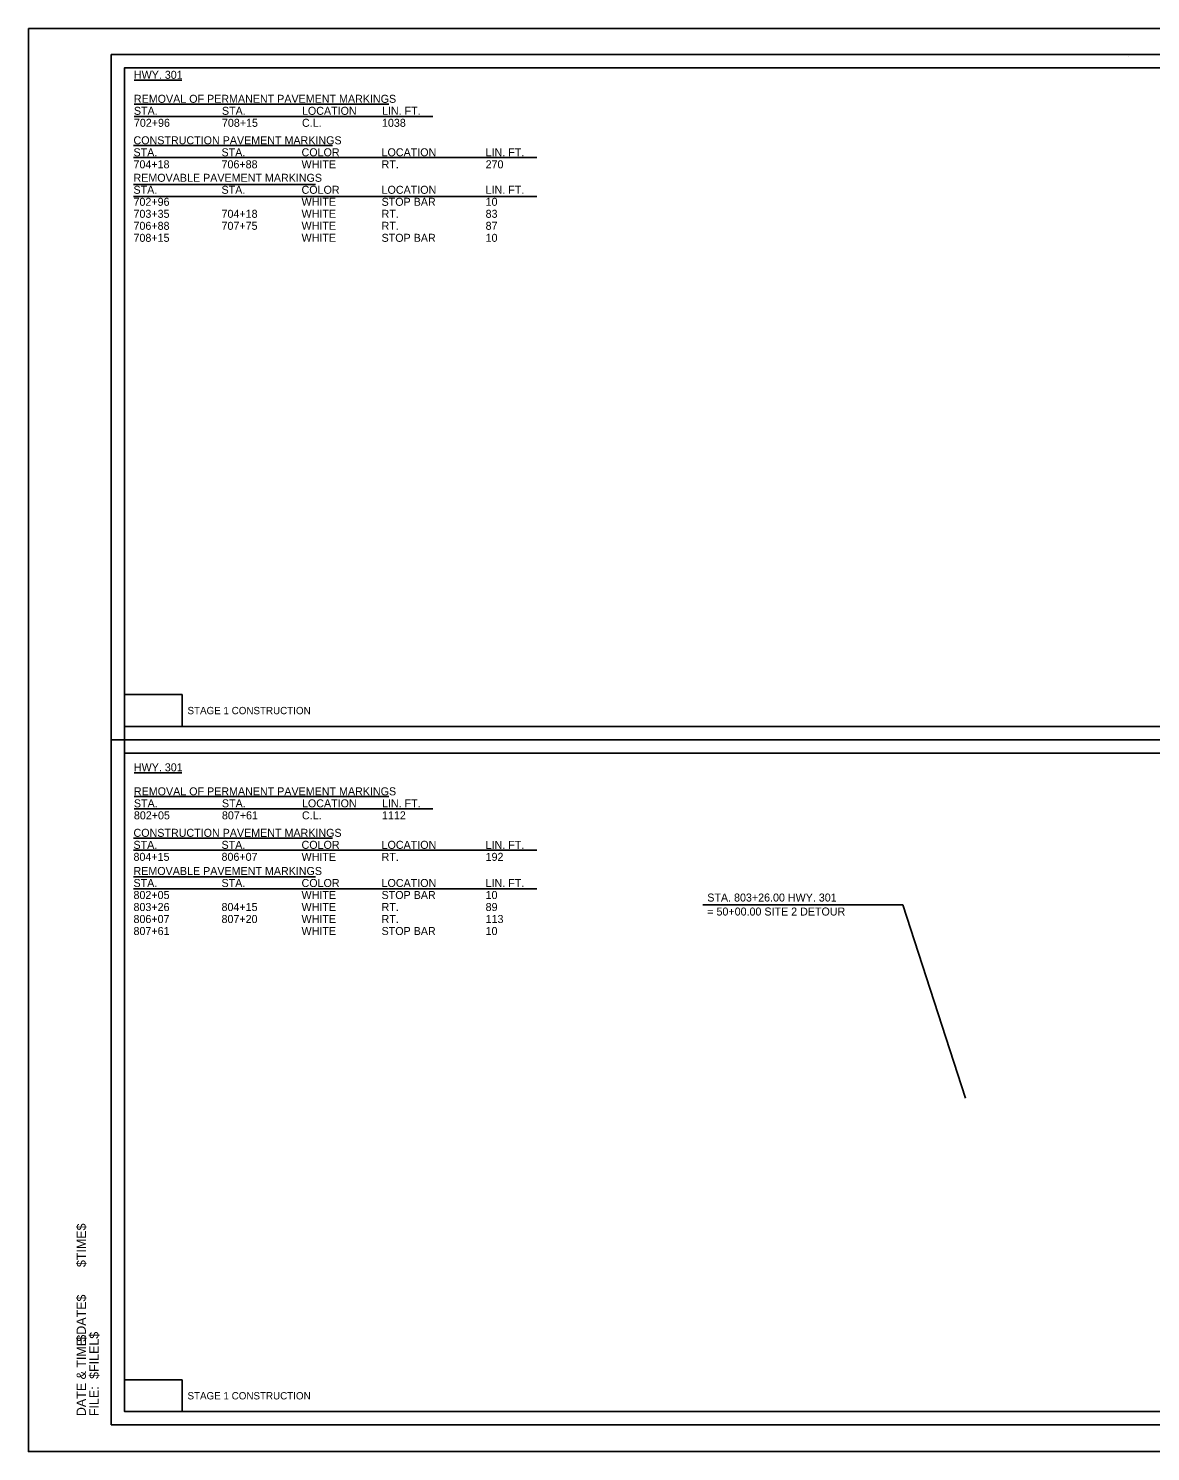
# Model space of a CAD drawing. Extents: x 1368648 to 1927880, y -1037443 to 380209.
# Drawn here: x 1373754 to 1374595, y 378686 to 379753 of the extents above; entities that cross this region are included whole.
import ezdxf

# ---------------------------------------------------------------- set-up
doc = ezdxf.new("R2010")
doc.units = 0
for name, color, linetype in [('Default', 7, 'Continuous'), ('R_Border', 7, 'Continuous'), ('R_Border Notes', 7, 'Continuous'), ('R_Detour Annot Limits', 7, 'Continuous'), ('R_No Plot', 7, 'Continuous')]:
    doc.layers.add(name, color=color, linetype=linetype)

msp = doc.modelspace()

# ---------------------------------------------------------------- linework, layer by layer
at = {"layer": 'Default'}
for p, q in [((1373833, 379713.9), (1373868.8, 379713.9)), ((1373833, 379696.1), (1374024, 379696.1)), ((1373833, 379686.7), (1374057, 379686.7)), ((1373832.7, 379664.9), (1373981.7, 379664.9)), ((1373832.7, 379655.9), (1374134.9, 379655.9)), ((1373832.7, 379635.7), (1373969.1, 379635.7)), ((1373832.7, 379626.7), (1374134.9, 379626.7)), ((1373833, 379194.8), (1373868.8, 379194.8)), ((1373833, 379177), (1374024, 379177)), ((1373833, 379167.7), (1374057, 379167.7)), ((1373832.7, 379145.9), (1373981.7, 379145.9)), ((1373832.7, 379136.9), (1374134.9, 379136.9)), ((1373832.7, 379116.7), (1373969.1, 379116.7)), ((1373832.7, 379107.7), (1374134.9, 379107.7))]:
    msp.add_line(p, q, dxfattribs=at)
for points in [[(1373825.9, 379229.6), (1373869, 379229.6), (1373869, 379253.4), (1373825.9, 379253.4), (1373825.9, 379229.6)], [(1373825.9, 378716), (1373869, 378716), (1373869, 378739.7), (1373825.9, 378739.7), (1373825.9, 378716)]]:
    msp.add_lwpolyline(points, dxfattribs=at)
at = {"layer": 'R_Border'}
for p, q in [((1373815.9, 379733.3), (1375396.8, 379733.3)), ((1373815.9, 378706), (1373815.9, 379733.3)), ((1374578.5, 379732), (1374578.5, 379732)), ((1374578.5, 379732), (1374578.5, 379732)), ((1375396.8, 379219.6), (1373815.9, 379219.6)), ((1373815.9, 378706), (1373815.9, 378706)), ((1375396.8, 378706), (1373815.9, 378706))]:
    msp.add_line(p, q, dxfattribs=at)
at = {"layer": 'R_Detour Annot Limits'}
msp.add_lwpolyline([(1374259.4, 379095.8), (1374409.4, 379095.8), (1374456.4, 378950.9)], dxfattribs=at)
at = {"layer": 'R_No Plot'}
for points in [[(1373753.8, 379752.7), (1375420.5, 379752.7), (1375420.5, 378686), (1373753.8, 378686)], [(1375386.8, 379229.6), (1373825.9, 379229.6), (1373825.9, 379723.3), (1375073.6, 379723.3), (1375073.6, 379673.9), (1375161.3, 379673.9), (1375281.8, 379673.9), (1375281.8, 379562.2), (1375386.8, 379562.2)], [(1375386.8, 379229.6), (1373825.9, 379229.6), (1373825.9, 379723.3), (1375073.6, 379723.3), (1375073.6, 379673.9), (1375161.3, 379673.9), (1375281.8, 379673.9), (1375281.8, 379562.2), (1375386.8, 379562.2)], [(1373825.9, 379723.3), (1375073.6, 379723.3), (1375073.6, 379673.9), (1375161.3, 379673.9), (1375281.8, 379673.9), (1375281.8, 379562.2), (1375386.8, 379562.2), (1375386.8, 378716), (1373825.9, 378716)], [(1373825.9, 379209.6), (1375386.8, 379209.6), (1375386.8, 378716), (1373825.9, 378716)], [(1373825.9, 379209.6), (1375386.8, 379209.6), (1375386.8, 378716), (1373825.9, 378716)]]:
    msp.add_lwpolyline(points, close=True, dxfattribs=at)

# ---------------------------------------------------------------- texts
at = {"layer": 'Default'}
for s, height, p in [('HWY. 301', 6, (1373832.9, 379715)), ('REMOVAL OF PERMANENT PAVEMENT MARKINGS', 6, (1373832.9, 379697)), ('STA.', 6, (1373832.9, 379688)), ('STA.', 6, (1373898.9, 379688)), ('LOCATION', 6, (1373958.9, 379688)), ('LIN. FT.', 6, (1374018.9, 379688)), ('702+96', 6, (1373832.9, 379679)), ('708+15', 6, (1373898.9, 379679)), ('C.L.', 6, (1373958.9, 379679)), ('1038', 6, (1374018.9, 379679)), ('CONSTRUCTION PAVEMENT MARKINGS', 6, (1373832.6, 379665.9)), ('STA.', 6, (1373832.6, 379656.9)), ('STA.', 6, (1373898.6, 379656.9)), ('COLOR', 6, (1373958.6, 379656.9)), ('LOCATION', 6, (1374018.6, 379656.9)), ('LIN. FT.', 6, (1374096.6, 379656.9)), ('704+18', 6, (1373832.6, 379647.9)), ('706+88', 6, (1373898.6, 379647.9)), ('WHITE', 6, (1373958.6, 379647.9)), ('RT.', 6, (1374018.6, 379647.9)), ('270', 6, (1374096.6, 379647.9)), ('STA.', 6, (1373832.6, 379628.8)), ('REMOVABLE PAVEMENT MARKINGS', 6, (1373832.6, 379637.8)), ('STA.', 6, (1373898.6, 379628.8)), ('COLOR', 6, (1373958.6, 379628.8)), ('LOCATION', 6, (1374018.6, 379628.8)), ('LIN. FT.', 6, (1374096.6, 379628.8)), ('702+96', 6, (1373832.6, 379619.8)), ('WHITE', 6, (1373958.6, 379619.8)), ('STOP BAR', 6, (1374018.6, 379619.8)), ('10', 6, (1374096.6, 379619.8)), ('703+35', 6, (1373832.6, 379610.8)), ('704+18', 6, (1373898.6, 379610.8)), ('WHITE', 6, (1373958.6, 379610.8)), ('RT.', 6, (1374018.6, 379610.8)), ('83', 6, (1374096.6, 379610.8)), ('706+88', 6, (1373832.6, 379601.8)), ('707+75', 6, (1373898.6, 379601.8)), ('WHITE', 6, (1373958.6, 379601.8)), ('RT.', 6, (1374018.6, 379601.8)), ('87', 6, (1374096.6, 379601.8)), ('708+15', 6, (1373832.6, 379592.8)), ('WHITE', 6, (1373958.6, 379592.8)), ('STOP BAR', 6, (1374018.6, 379592.8)), ('10', 6, (1374096.6, 379592.8)), ('  STAGE 1 CONSTRUCTION', 5.5, (1373869, 379238.7)), ('HWY. 301', 6, (1373832.9, 379195.9)), ('REMOVAL OF PERMANENT PAVEMENT MARKINGS', 6, (1373832.9, 379177.9)), ('STA.', 6, (1373832.9, 379168.9)), ('802+05', 6, (1373832.9, 379159.9)), ('STA.', 6, (1373898.9, 379168.9)), ('807+61', 6, (1373898.9, 379159.9)), ('C.L.', 6, (1373958.9, 379159.9)), ('LOCATION', 6, (1373958.9, 379168.9)), ('LIN. FT.', 6, (1374018.9, 379168.9)), ('1112', 6, (1374018.9, 379159.9)), ('CONSTRUCTION PAVEMENT MARKINGS', 6, (1373832.6, 379146.8)), ('STA.', 6, (1373832.6, 379137.8)), ('STA.', 6, (1373898.6, 379137.8)), ('COLOR', 6, (1373958.6, 379137.8)), ('LOCATION', 6, (1374018.6, 379137.8)), ('LIN. FT.', 6, (1374096.6, 379137.8)), ('804+15', 6, (1373832.6, 379128.8)), ('806+07', 6, (1373898.6, 379128.8)), ('WHITE', 6, (1373958.6, 379128.8)), ('RT.', 6, (1374018.6, 379128.8)), ('192', 6, (1374096.6, 379128.8)), ('REMOVABLE PAVEMENT MARKINGS', 6, (1373832.6, 379118.2)), ('STA.', 6, (1373832.6, 379109.2)), ('STA.', 6, (1373898.6, 379109.2)), ('COLOR', 6, (1373958.6, 379109.2)), ('LOCATION', 6, (1374018.6, 379109.2)), ('LIN. FT.', 6, (1374096.6, 379109.2)), ('802+05', 6, (1373832.6, 379100.2)), ('WHITE', 6, (1373958.6, 379100.2)), ('STOP BAR', 6, (1374018.6, 379100.2)), ('10', 6, (1374096.6, 379100.2)), ('803+26', 6, (1373832.6, 379091.2)), ('804+15', 6, (1373898.6, 379091.2)), ('WHITE', 6, (1373958.6, 379091.2)), ('RT.', 6, (1374018.6, 379091.2)), ('89', 6, (1374096.6, 379091.2)), ('806+07', 6, (1373832.6, 379082.2)), ('807+20', 6, (1373898.6, 379082.2)), ('WHITE', 6, (1373958.6, 379082.2)), ('RT.', 6, (1374018.6, 379082.2)), ('113', 6, (1374096.6, 379082.2)), ('807+61', 6, (1373832.6, 379073.2)), ('WHITE', 6, (1373958.6, 379073.2)), ('STOP BAR', 6, (1374018.6, 379073.2)), ('10', 6, (1374096.6, 379073.2)), ('  STAGE 1 CONSTRUCTION', 5.5, (1373869, 378725.1))]:
    msp.add_text(s, height=height, dxfattribs=at).set_placement(p)
at = {"layer": 'R_Border Notes'}
for s, height, p in [('$TIME$', 6.98, (1373796.9, 378824.3)), ('$DATE$', 6.98, (1373796.9, 378768.4)), ('DATE & TIME:', 6.984, (1373796.9, 378712.6)), ('$FILEL$', 6.98, (1373806.5, 378740.5)), ('FILE: ', 6.98, (1373806.5, 378712.6))]:
    msp.add_text(s, height=height, rotation=90, dxfattribs=at).set_placement(p)
at = {"layer": 'R_Detour Annot Limits'}
for s, p in [('STA. 803+26.00 HWY. 301', (1374262.8, 379098.3)), ('= 50+00.00 SITE 2 DETOUR', (1374262.8, 379087.8))]:
    msp.add_text(s, height=6, rotation=0.0001, dxfattribs=at).set_placement(p)

doc.saveas('drawing.dxf')
